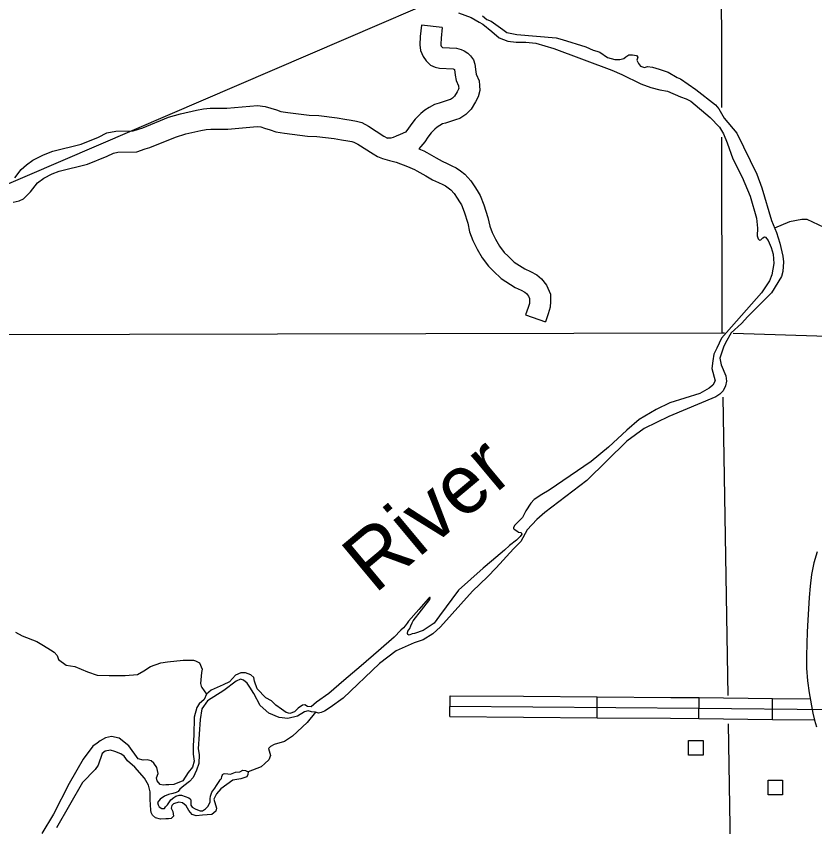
# Model space of a CAD drawing. Extents: x 1369885 to 1370219, y 379980 to 380218.
# Drawn here: x 1370027.38 to 1370050.18, y 380071.42 to 380094.55 of the extents above; entities that cross this region are included whole.
import ezdxf

# ---------------------------------------------------------------- set-up
doc = ezdxf.new("R2010")
doc.units = 0
for name, color, linetype in [('Level 10', 7, 'Continuous'), ('Level 32', 7, 'Continuous'), ('Level 35', 7, 'Continuous'), ('Level 45', 7, 'Continuous'), ('Level 46', 7, 'Continuous'), ('Level 5', 7, 'Continuous'), ('Level 56', 7, 'Continuous'), ('Page Text', 7, 'Continuous')]:
    doc.layers.add(name, color=color, linetype=linetype)

msp = doc.modelspace()

# ---------------------------------------------------------------- linework, layer by layer
at = {"layer": 'Level 10'}
msp.add_lwpolyline([(1370050.241, 380079.27), (1370050.151, 380078.948), (1370050.085, 380078.617), (1370050.045, 380078.287), (1370050.018, 380077.963), (1370049.998, 380077.639), (1370049.979, 380077.313), (1370049.96, 380076.981), (1370049.945, 380076.642), (1370049.936, 380076.298), (1370049.94, 380075.942), (1370049.967, 380075.587), (1370050.014, 380075.24), (1370050.121, 380074.663), (1370050.168, 380074.458), (1370050.222, 380074.268)], dxfattribs=at)
at = {"layer": 'Level 32'}
for p, q in [((1370046.866, 380074.51), (1370046.873, 380075.107)), ((1370048.966, 380074.485), (1370048.973, 380075.082))]:
    msp.add_line(p, q, dxfattribs=at)
for points in [[(1370046.873, 380075.107), (1370048.973, 380075.082)], [(1370048.973, 380075.082), (1370050.046, 380075.069)], [(1370046.869, 380074.808), (1370050.608, 380074.764)], [(1370046.866, 380074.51), (1370048.966, 380074.485)], [(1370048.966, 380074.485), (1370050.164, 380074.471)]]:
    msp.add_lwpolyline(points, dxfattribs=at)
at = {"layer": 'Level 35'}
for points in [[(1370040.006, 380094.65), (1370040.369, 380094.518), (1370040.592, 380094.383), (1370040.701, 380094.32), (1370040.961, 380094.119), (1370041.17, 380093.935), (1370041.412, 380093.843), (1370041.654, 380093.814), (1370041.93, 380093.814), (1370042.211, 380093.782), (1370042.732, 380093.634), (1370044.387, 380093.015), (1370044.669, 380092.888), (1370045.209, 380092.621), (1370045.497, 380092.517), (1370045.751, 380092.448), (1370045.97, 380092.413), (1370046.341, 380092.253), (1370046.505, 380092.198), (1370046.643, 380092.127), (1370047.193, 380091.661), (1370047.456, 380091.382), (1370047.569, 380091.198), (1370047.672, 380090.938)], [(1370040.694, 380094.562), (1370040.813, 380094.454), (1370040.939, 380094.408), (1370041.072, 380094.316), (1370041.268, 380094.172), (1370041.389, 380094.085), (1370041.671, 380094.033), (1370042.79, 380093.933), (1370042.966, 380093.891), (1370043.642, 380093.682), (1370043.855, 380093.578), (1370043.959, 380093.555), (1370044.045, 380093.526), (1370044.259, 380093.37), (1370044.466, 380093.318), (1370044.61, 380093.318), (1370044.725, 380093.342), (1370044.783, 380093.393), (1370044.864, 380093.445), (1370044.973, 380093.445), (1370045.088, 380093.434), (1370045.129, 380093.382), (1370045.094, 380093.301), (1370045.14, 380093.203), (1370045.204, 380093.128), (1370045.313, 380093.088), (1370045.399, 380093.117), (1370045.544, 380093.099), (1370045.739, 380093.036), (1370045.993, 380092.955), (1370046.251, 380092.802), (1370046.34, 380092.76), (1370046.779, 380092.462), (1370047.345, 380092.02), (1370047.44, 380091.904), (1370047.591, 380091.645), (1370047.95, 380091.21)], [(1370047.95, 380091.21), (1370048.521, 380090.039), (1370048.668, 380089.657), (1370048.939, 380088.72), (1370049.084, 380088.378), (1370049.181, 380088.078), (1370049.268, 380087.702), (1370049.281, 380087.539), (1370049.261, 380087.267), (1370049.226, 380087.123), (1370048.939, 380086.662), (1370048.267, 380085.984), (1370048.081, 380085.781), (1370047.786, 380085.515), (1370047.627, 380085.232), (1370047.572, 380085.103), (1370047.467, 380084.795), (1370047.507, 380084.604), (1370047.635, 380084.285), (1370047.658, 380084.14), (1370047.632, 380084.001), (1370047.557, 380083.859), (1370047.469, 380083.761), (1370047.356, 380083.69), (1370046.012, 380083.125), (1370045.31, 380082.788), (1370044.812, 380082.423), (1370043.67, 380081.302), (1370042.467, 380080.392), (1370042.238, 380080.19), (1370041.965, 380079.895), (1370041.781, 380079.557), (1370041.576, 380079.348), (1370041.081, 380078.811), (1370040.834, 380078.549), (1370040.406, 380078.141), (1370039.491, 380077.129), (1370039.271, 380076.931), (1370039.002, 380076.753), (1370038.743, 380076.67), (1370038.225, 380076.445), (1370037.752, 380076.079), (1370036.713, 380075.095)], [(1370047.672, 380090.938), (1370047.84, 380090.485), (1370048.107, 380089.955), (1370048.33, 380089.415), (1370048.508, 380088.791), (1370048.544, 380088.501), (1370048.535, 380088.286), (1370048.558, 380088.195), (1370048.602, 380088.164), (1370048.634, 380088.165), (1370048.691, 380088.231), (1370048.742, 380088.252), (1370048.774, 380088.245), (1370048.849, 380088.152), (1370048.934, 380087.955), (1370048.988, 380087.761), (1370049.008, 380087.491), (1370048.954, 380087.174), (1370048.888, 380086.997), (1370048.651, 380086.656), (1370047.518, 380085.368), (1370047.378, 380085.076), (1370047.299, 380084.911), (1370047.27, 380084.714), (1370047.241, 380084.5), (1370047.333, 380084.146), (1370047.27, 380084.024), (1370047.16, 380083.937), (1370046.899, 380083.78), (1370046.041, 380083.514), (1370045.647, 380083.328), (1370045.16, 380083.038), (1370044.812, 380082.736), (1370044.287, 380082.255), (1370043.792, 380081.843), (1370042.596, 380081.025), (1370042.381, 380080.906), (1370042.17, 380080.764), (1370042.074, 380080.653), (1370041.929, 380080.433), (1370041.831, 380080.244), (1370041.616, 380080.024), (1370041.581, 380079.957), (1370041.579, 380079.931), (1370041.593, 380079.911), (1370041.668, 380079.87), (1370041.718, 380079.83), (1370041.796, 380079.815), (1370041.81, 380079.769), (1370041.764, 380079.702), (1370041.663, 380079.595), (1370041.46, 380079.444), (1370041.321, 380079.311), (1370040.953, 380079), (1370040.708, 380078.8), (1370040.011, 380078.174), (1370039.46, 380077.437), (1370039.311, 380077.235), (1370039, 380077.018), (1370038.746, 380076.934), (1370038.682, 380076.925), (1370038.598, 380076.885), (1370038.557, 380076.908), (1370038.546, 380076.94), (1370038.557, 380077.001), (1370038.618, 380077.076), (1370038.647, 380077.154), (1370038.682, 380077.244), (1370038.708, 380077.299), (1370038.951, 380077.598), (1370039.184, 380077.908), (1370039.2, 380077.951), (1370039.198, 380077.963), (1370039.186, 380077.963), (1370039.16, 380077.946), (1370039.141, 380077.929), (1370038.876, 380077.618), (1370038.58, 380077.288), (1370038.537, 380077.227), (1370038.488, 380077.154), (1370038.436, 380077.101), (1370038.358, 380077.031)], [(1370055.125, 380089.196), (1370054.552, 380089.09), (1370054.101, 380089.045), (1370053.215, 380088.906), (1370052.257, 380088.813), (1370051.977, 380088.745), (1370051.522, 380088.548), (1370050.977, 380088.447), (1370050.563, 380088.483), (1370050.442, 380088.519), (1370049.963, 380088.751), (1370049.804, 380088.751), (1370049.456, 380088.684), (1370049.029, 380088.504)], [(1370038.358, 380077.031), (1370038.17, 380076.833), (1370037.721, 380076.441), (1370037.228, 380076.01), (1370036.73, 380075.59), (1370036.308, 380075.22), (1370035.954, 380074.976), (1370035.804, 380074.843), (1370035.699, 380074.849), (1370035.624, 380074.901), (1370035.555, 380074.889), (1370035.433, 380074.808), (1370035.328, 380074.704), (1370035.189, 380074.651), (1370035.085, 380074.68), (1370034.952, 380074.773), (1370034.795, 380074.895), (1370034.673, 380075.017), (1370034.505, 380075.104), (1370034.262, 380075.353), (1370034.181, 380075.574), (1370034.16, 380075.677), (1370034.082, 380075.755), (1370033.931, 380075.81), (1370033.792, 380075.811), (1370033.642, 380075.748), (1370033.474, 380075.556), (1370033.291, 380075.474), (1370032.946, 380075.321), (1370032.818, 380075.204), (1370032.747, 380075.052), (1370032.601, 380074.925), (1370032.536, 380074.824), (1370032.459, 380074.551), (1370032.455, 380074.033), (1370032.437, 380073.744), (1370032.43, 380073.493), (1370032.462, 380073.296), (1370032.412, 380073.118), (1370032.286, 380072.969), (1370032.14, 380072.735), (1370031.881, 380072.628), (1370031.734, 380072.62), (1370031.65, 380072.615), (1370031.574, 380072.608), (1370031.495, 380072.623), (1370031.409, 380072.73), (1370031.388, 380072.814), (1370031.429, 380072.936), (1370031.393, 380073.114), (1370031.307, 380073.234), (1370031.236, 380073.3), (1370031.124, 380073.333), (1370031.004, 380073.317), (1370030.867, 380073.356), (1370030.601, 380073.734), (1370030.316, 380073.952), (1370030.103, 380073.998), (1370029.929, 380073.961), (1370029.782, 380073.876), (1370029.692, 380073.808), (1370029.567, 380073.722), (1370029.296, 380073.348), (1370028.892, 380072.66), (1370028.448, 380071.779)], [(1370027.365, 380076.972), (1370027.554, 380076.87), (1370027.972, 380076.703), (1370028.16, 380076.597), (1370028.364, 380076.474), (1370028.466, 380076.403), (1370028.547, 380076.312), (1370028.586, 380076.19), (1370028.811, 380076.035), (1370029.059, 380075.992), (1370029.415, 380075.839), (1370029.695, 380075.747), (1370030.031, 380075.739), (1370030.494, 380075.734), (1370030.844, 380075.763), (1370031.028, 380075.866), (1370031.216, 380075.998), (1370031.511, 380076.095), (1370031.696, 380076.123), (1370032.148, 380076.176), (1370032.438, 380076.177), (1370032.502, 380076.159), (1370032.617, 380076.101), (1370032.694, 380075.916), (1370032.671, 380075.821)], [(1370036.713, 380075.095), (1370036.34, 380074.821), (1370036.184, 380074.72), (1370036.09, 380074.682), (1370036.011, 380074.667), (1370035.927, 380074.689), (1370035.81, 380074.704), (1370035.711, 380074.727), (1370035.607, 380074.698), (1370035.415, 380074.576), (1370035.137, 380074.506), (1370034.888, 380074.541), (1370034.592, 380074.663), (1370034.343, 380074.878), (1370034.169, 380075.22), (1370034.053, 380075.4), (1370033.978, 380075.521), (1370033.874, 380075.603), (1370033.781, 380075.632), (1370033.659, 380075.574), (1370033.307, 380075.306), (1370032.842, 380075.016), (1370032.681, 380074.782), (1370032.63, 380074.486), (1370032.579, 380073.647), (1370032.604, 380073.479)], [(1370032.671, 380075.821), (1370032.641, 380075.506), (1370032.663, 380075.435), (1370032.684, 380075.395), (1370032.818, 380075.204)], [(1370035.927, 380074.689), (1370035.685, 380074.394), (1370035.272, 380074.003), (1370035.043, 380073.853), (1370034.747, 380073.764), (1370034.638, 380073.709), (1370034.584, 380073.651), (1370034.642, 380073.45), (1370034.59, 380073.333), (1370034.482, 380073.222), (1370034.376, 380073.132), (1370034.005, 380072.989)], [(1370031.209, 380072.203), (1370031.203, 380072.414), (1370031.162, 380072.608), (1370031.044, 380072.812), (1370030.764, 380073.118), (1370030.56, 380073.301), (1370030.459, 380073.438), (1370030.367, 380073.505), (1370030.199, 380073.566), (1370030.072, 380073.606), (1370029.925, 380073.581), (1370029.837, 380073.507), (1370029.719, 380073.183), (1370029.631, 380073.057)], [(1370032.604, 380073.479), (1370032.591, 380073.223), (1370032.525, 380073.035), (1370032.433, 380072.826), (1370032.332, 380072.714), (1370032.164, 380072.587), (1370032.052, 380072.491), (1370032.006, 380072.427), (1370031.943, 380072.395), (1370031.851, 380072.371), (1370031.727, 380072.343), (1370031.615, 380072.292), (1370031.488, 380072.206), (1370031.416, 380072.109), (1370031.432, 380072.046), (1370031.462, 380071.99), (1370031.538, 380071.946), (1370031.615, 380071.946), (1370031.64, 380071.987), (1370031.696, 380072.043), (1370031.757, 380072.129), (1370031.798, 380072.185), (1370031.879, 380072.256), (1370031.94, 380072.297), (1370032.032, 380072.318), (1370032.103, 380072.318), (1370032.205, 380072.287), (1370032.306, 380072.246), (1370032.357, 380072.211), (1370032.367, 380072.17), (1370032.367, 380072.038), (1370032.403, 380071.982), (1370032.489, 380071.931), (1370032.556, 380071.9), (1370032.632, 380071.875), (1370032.703, 380071.88), (1370032.789, 380071.931), (1370032.856, 380071.997), (1370032.917, 380072.119), (1370032.922, 380072.216), (1370032.932, 380072.292), (1370032.967, 380072.404), (1370033.054, 380072.521), (1370033.095, 380072.597), (1370033.171, 380072.714), (1370033.201, 380072.76), (1370033.237, 380072.796), (1370033.252, 380072.852), (1370033.262, 380072.887), (1370033.278, 380072.913), (1370033.303, 380072.933), (1370033.334, 380072.943), (1370033.42, 380072.928), (1370033.496, 380072.923), (1370033.639, 380072.979), (1370033.761, 380072.989), (1370033.847, 380073.04), (1370033.929, 380073.03), (1370034.005, 380072.989)], [(1370029.631, 380073.057), (1370029.278, 380072.685), (1370028.527, 380071.387)], [(1370034.005, 380072.989), (1370033.995, 380072.908), (1370033.964, 380072.847), (1370033.796, 380072.791), (1370033.568, 380072.75), (1370033.227, 380072.501), (1370033.095, 380072.363), (1370033.023, 380072.211), (1370033.095, 380071.956), (1370033.079, 380071.87), (1370032.967, 380071.773), (1370032.703, 380071.753), (1370032.52, 380071.737), (1370032.403, 380071.773), (1370032.306, 380071.885), (1370032.23, 380072.022), (1370032.133, 380072.104), (1370032.022, 380072.119), (1370031.869, 380072.073), (1370031.823, 380072.027), (1370031.808, 380071.956), (1370031.849, 380071.854), (1370031.868, 380071.719), (1370031.808, 380071.661), (1370031.732, 380071.646), (1370031.655, 380071.646), (1370031.503, 380071.641), (1370031.355, 380071.676), (1370031.274, 380071.753), (1370031.238, 380071.829), (1370031.223, 380071.895), (1370031.209, 380072.203)], [(1370028.448, 380071.779), (1370028.115, 380071.231)]]:
    msp.add_lwpolyline(points, dxfattribs=at)
at = {"layer": 'Level 45'}
for p, q in [((1370039.761, 380074.563), (1370039.765, 380075.159)), ((1370043.961, 380074.532), (1370043.965, 380075.128))]:
    msp.add_line(p, q, dxfattribs=at)
for points in [[(1370039.765, 380075.159), (1370041.865, 380075.144)], [(1370041.865, 380075.144), (1370043.965, 380075.128)], [(1370043.965, 380075.128), (1370046.066, 380075.113)], [(1370046.066, 380075.113), (1370046.873, 380075.107)], [(1370039.763, 380074.861), (1370046.869, 380074.808)], [(1370039.761, 380074.563), (1370041.861, 380074.547)], [(1370041.861, 380074.547), (1370043.961, 380074.532)], [(1370043.961, 380074.532), (1370046.061, 380074.516)], [(1370046.061, 380074.516), (1370046.866, 380074.51)]]:
    msp.add_lwpolyline(points, dxfattribs=at)
at = {"layer": 'Level 46'}
for points in [[(1370039.542, 380094.232), (1370038.949, 380094.297), (1370038.913, 380093.969), (1370038.902, 380093.735), (1370038.918, 380093.569), (1370038.994, 380093.4), (1370039.079, 380093.281), (1370039.207, 380093.158), (1370039.343, 380093.099), (1370039.463, 380093.068), (1370039.85, 380093.051), (1370039.856, 380093.049), (1370039.878, 380093.038), (1370039.894, 380093.028), (1370039.909, 380092.873), (1370039.94, 380092.718), (1370040.009, 380092.562), (1370040.011, 380092.537), (1370040.013, 380092.495), (1370040.006, 380092.468), (1370039.97, 380092.396), (1370039.89, 380092.268), (1370039.834, 380092.208), (1370039.78, 380092.173), (1370039.743, 380092.161), (1370039.63, 380092.127), (1370039.459, 380092.071), (1370039.32, 380092.029), (1370039.166, 380091.946), (1370039.047, 380091.869), (1370038.927, 380091.775), (1370038.772, 380091.613), (1370038.644, 380091.449), (1370038.563, 380091.329), (1370038.49, 380091.242), (1370038.342, 380091.18), (1370038.23, 380091.125), (1370038.144, 380091.09), (1370038.071, 380091.074), (1370037.98, 380091.073)], [(1370039.542, 380094.232), (1370039.508, 380093.923), (1370039.5, 380093.75), (1370039.503, 380093.724), (1370039.514, 380093.698), (1370039.532, 380093.673), (1370039.542, 380093.664), (1370039.552, 380093.661), (1370039.948, 380093.644), (1370040.081, 380093.605), (1370040.169, 380093.559), (1370040.271, 380093.498), (1370040.345, 380093.424), (1370040.432, 380093.307), (1370040.477, 380093.185), (1370040.5, 380092.962), (1370040.513, 380092.899), (1370040.596, 380092.708), (1370040.606, 380092.577), (1370040.615, 380092.429), (1370040.565, 380092.254), (1370040.493, 380092.106), (1370040.364, 380091.9), (1370040.218, 380091.747), (1370040.043, 380091.632), (1370039.924, 380091.592), (1370039.807, 380091.557), (1370039.638, 380091.502), (1370039.551, 380091.476), (1370039.47, 380091.432), (1370039.393, 380091.382), (1370039.328, 380091.332), (1370039.224, 380091.222), (1370039.127, 380091.098), (1370039.041, 380090.97), (1370038.875, 380090.771)], [(1370027.673, 380090.309), (1370027.859, 380090.44), (1370028.161, 380090.594), (1370028.424, 380090.699), (1370029.234, 380090.895), (1370029.729, 380091.102), (1370029.971, 380091.22), (1370030.225, 380091.266), (1370030.719, 380091.276), (1370030.876, 380091.332), (1370030.993, 380091.369), (1370031.73, 380091.668), (1370032.068, 380091.768), (1370032.532, 380091.872), (1370032.724, 380091.91), (1370032.914, 380091.924), (1370033.396, 380091.924), (1370034.271, 380092.006), (1370034.489, 380091.975), (1370034.646, 380091.929), (1370034.812, 380091.875), (1370034.937, 380091.834), (1370035.131, 380091.8), (1370035.74, 380091.727), (1370036.017, 380091.715), (1370036.541, 380091.65), (1370036.765, 380091.614), (1370036.946, 380091.585), (1370037.095, 380091.559), (1370037.245, 380091.518), (1370037.435, 380091.415), (1370037.875, 380091.132), (1370037.98, 380091.073)], [(1370027.987, 380089.8), (1370028.168, 380089.928), (1370028.408, 380090.05), (1370028.606, 380090.13), (1370029.42, 380090.326), (1370029.975, 380090.558), (1370030.159, 380090.647), (1370030.285, 380090.67), (1370030.826, 380090.682), (1370031.066, 380090.766), (1370031.197, 380090.808), (1370031.927, 380091.104), (1370032.219, 380091.19), (1370032.655, 380091.288), (1370032.803, 380091.318), (1370032.936, 380091.327), (1370033.424, 380091.327), (1370034.257, 380091.406), (1370034.362, 380091.391), (1370034.47, 380091.359), (1370034.627, 380091.308), (1370034.79, 380091.254), (1370035.044, 380091.209), (1370035.692, 380091.132), (1370035.967, 380091.12), (1370036.458, 380091.059), (1370036.671, 380091.025), (1370036.848, 380090.997), (1370036.964, 380090.976), (1370037.021, 380090.961), (1370037.131, 380090.901), (1370037.568, 380090.62), (1370037.691, 380090.551), (1370037.839, 380090.492), (1370038.041, 380090.436), (1370038.231, 380090.383), (1370038.548, 380090.264), (1370038.751, 380090.173), (1370038.813, 380090.139), (1370039.07, 380089.992), (1370039.267, 380089.881), (1370039.437, 380089.804), (1370039.556, 380089.75), (1370039.638, 380089.706), (1370039.711, 380089.657), (1370039.787, 380089.598), (1370039.887, 380089.489), (1370039.969, 380089.361), (1370040.036, 380089.257), (1370040.09, 380089.167), (1370040.169, 380088.969), (1370040.269, 380088.649), (1370040.325, 380088.398), (1370040.415, 380088.147), (1370040.537, 380087.904), (1370040.68, 380087.659), (1370040.859, 380087.417), (1370041.007, 380087.272), (1370041.226, 380087.063), (1370041.62, 380086.814), (1370041.796, 380086.735), (1370041.896, 380086.681), (1370041.944, 380086.638), (1370042.005, 380086.563), (1370042.034, 380086.497), (1370042.034, 380086.427), (1370042.03, 380086.35), (1370041.996, 380086.241), (1370041.923, 380086.026), (1370042.488, 380085.833)], [(1370038.875, 380090.771), (1370039.015, 380090.708), (1370039.103, 380090.661), (1370039.365, 380090.511), (1370039.537, 380090.414), (1370039.684, 380090.347), (1370039.819, 380090.286), (1370039.944, 380090.22), (1370040.061, 380090.142), (1370040.192, 380090.039), (1370040.363, 380089.854), (1370040.471, 380089.683), (1370040.543, 380089.573), (1370040.627, 380089.433), (1370040.732, 380089.169), (1370040.846, 380088.803), (1370040.899, 380088.564), (1370040.965, 380088.382), (1370041.062, 380088.188), (1370041.178, 380087.988), (1370041.31, 380087.81), (1370041.422, 380087.701), (1370041.595, 380087.535), (1370041.903, 380087.341), (1370042.061, 380087.27), (1370042.239, 380087.174), (1370042.374, 380087.055), (1370042.521, 380086.876), (1370042.63, 380086.619), (1370042.63, 380086.413), (1370042.623, 380086.247), (1370042.564, 380086.057), (1370042.488, 380085.833)], [(1370027.342, 380089.936), (1370027.527, 380090.18), (1370027.673, 380090.309)], [(1370027.295, 380089.242), (1370027.463, 380089.284), (1370027.59, 380089.34), (1370027.793, 380089.544), (1370027.987, 380089.8)]]:
    msp.add_lwpolyline(points, dxfattribs=at)
at = {"layer": 'Level 5'}
for points in [[(1370047.491, 380101.993), (1370047.513, 380091.942)], [(1370047.515, 380091.096), (1370047.527, 380085.517)], [(1370026.377, 380085.471), (1370047.527, 380085.517)], [(1370047.527, 380085.517), (1370047.599, 380085.515)], [(1370047.851, 380085.507), (1370053.821, 380085.32)], [(1370047.556, 380083.678), (1370047.69, 380075.162)], [(1370047.703, 380074.358), (1370047.861, 380064.404)]]:
    msp.add_lwpolyline(points, dxfattribs=at)
at = {"layer": 'Level 56'}
for points in [[(1370046.573, 380073.465), (1370046.573, 380073.879), (1370046.988, 380073.879), (1370046.988, 380073.465)], [(1370048.844, 380072.335), (1370048.844, 380072.749), (1370049.259, 380072.749), (1370049.259, 380072.335)]]:
    msp.add_lwpolyline(points, close=True, dxfattribs=at)
at = {"layer": 'Page Text'}
msp.add_lwpolyline([(1370049.822, 380099.52), (1369957.219, 380059.71)], dxfattribs=at)

# ---------------------------------------------------------------- texts
at = {"layer": 'Level 35'}
msp.add_text('River', height=1.6802, rotation=39.8249, dxfattribs=at).set_placement((1370037.613, 380078.046))

doc.saveas('drawing.dxf')
